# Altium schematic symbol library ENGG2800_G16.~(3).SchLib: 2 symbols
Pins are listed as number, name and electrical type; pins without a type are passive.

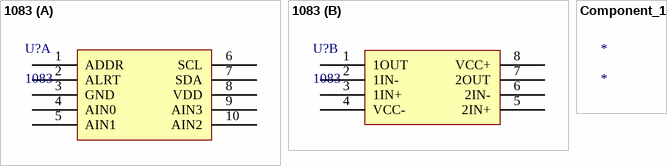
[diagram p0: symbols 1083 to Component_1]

## 1083
designator U?
EVAL BOARD ADS1115 16-BIT ADC; Manufacturer: Adafruit Industries; Description: EVAL BOARD ADS1015 12-BIT ADC; Number of Bits: 12; Evaluation Kit: Yes; Number of A/D Converters: 1; Sampling Rate: 3300S/s; Interface: I2C,Serial
part A pins: 1 ADDR, 2 ALRT, 3 GND, 4 AIN0, 5 AIN1, 6 SCL, 7 SDA, 8 VDD, 9 AIN3, 10 AIN2
part B pins: 1 1OUT, 2 1IN-, 3 1IN+, 4 VCC-, 5 2IN+, 6 2IN-, 7 2OUT, 8 VCC+

## Component_1
designator *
